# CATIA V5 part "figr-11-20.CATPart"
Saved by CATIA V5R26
Part number: Part5
Bounding box of the stored display mesh (mm): x -70 to 70, y -150 to 0, z -1.939 to 20.996
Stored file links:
  D:\_Deepak\CATIA\CATIA V5-6R2016_Deepak\Resources\Part files\Partfiles\c11_catia_v5_6r2016_prt\figr-11-20.CATPart
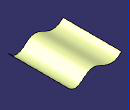
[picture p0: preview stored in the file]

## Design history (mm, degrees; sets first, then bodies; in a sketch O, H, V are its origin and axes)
Body1 (main body)
  Sketch1 on zx-plane, origin (0, 0, 0), H (-1, 0, 0), V (0, 0, 1)
    spline S1 through (-70, 10) (-40, 0) (-10, 20) (30, 10) (70, 20)
  Extrude1: Element1 Sketch1, Lim1 150, Lim2 0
